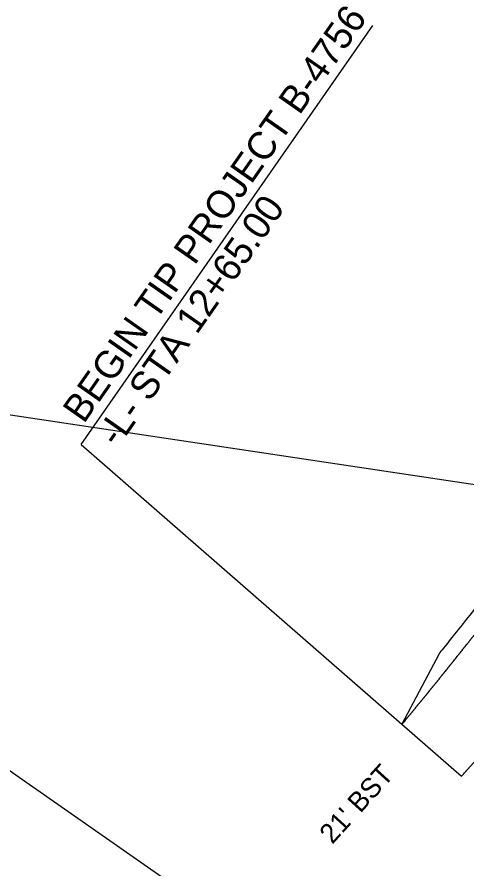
# Model space of a CAD drawing. Extents: x 1731327 to 1735374, y 884856 to 889832.
# Drawn here: x 1731918.7 to 1732032.5, y 885272.3 to 885487.7 of the extents above; entities that cross this region are included whole.
import ezdxf

# ---------------------------------------------------------------- set-up
doc = ezdxf.new("R2010")
doc.units = 0
for name, color, linetype in [('Exist Horizontal Baseline Alignment', 7, 'Continuous'), ('Exist Other Culture Area Outline', 7, 'Continuous'), ('Exist Other Culture Sign Text', 7, 'Continuous'), ('Exist Roads EOP', 7, 'Continuous'), ('Exist Structure Minor Pipes RCP 24 Inch', 7, 'Continuous'), ('Exist Structure Minor Pipes RCP 24 Inch Text', 7, 'Continuous')]:
    doc.layers.add(name, color=color, linetype=linetype)

msp = doc.modelspace()

# ---------------------------------------------------------------- linework, layer by layer
at = {"layer": 'Exist Other Culture Area Outline'}
for q in [(1732008.71, 885485.55), (1732016.04, 885308.91)]:
    msp.add_line((1731934.91, 885379.64), q, dxfattribs=at)
msp.add_lwpolyline([(1732238.91, 886072.74), (1731769.46, 885400.02), (1732118.14, 885156.7), (1732587.59, 885829.41)], close=True, dxfattribs=at)
at = {"layer": 'Exist Other Culture Sign Text'}
msp.add_lwpolyline([(1731775.28, 885408.36), (1732121.12, 885356.5), (1732232.4, 885320.42)], dxfattribs=at)
at = {"layer": 'Exist Structure Minor Pipes RCP 24 Inch'}
for p, q in [((1732025.45, 885326.74), (1732016.04, 885308.91)), ((1732016.04, 885308.91), (1732031.11, 885295.77))]:
    msp.add_line(p, q, dxfattribs=at)
for points, degree in [([(1732043.86, 885350.1), (1732038.81, 885343.58), (1732032.68, 885335.78), (1732026.49, 885328.04), (1732025.45, 885326.74)], 3), ([(1732036.84, 885334.63), (1732036.79, 885334.56), (1732036.73, 885334.49), (1732036.68, 885334.43), (1732036.54, 885334.25), (1732036.4, 885334.08), (1732036.27, 885333.9), (1732036.13, 885333.73), (1732035.99, 885333.55), (1732035.85, 885333.38), (1732035.71, 885333.2), (1732035.57, 885333.02), (1732035.43, 885332.85), (1732035.29, 885332.67), (1732035.15, 885332.5), (1732035.02, 885332.32), (1732034.88, 885332.15), (1732034.74, 885331.97), (1732034.6, 885331.8), (1732034.46, 885331.62), (1732034.32, 885331.45), (1732034.18, 885331.27), (1732034.04, 885331.09), (1732033.9, 885330.92), (1732033.76, 885330.74), (1732033.62, 885330.57), (1732033.48, 885330.39), (1732033.35, 885330.22), (1732033.21, 885330.04), (1732033.07, 885329.87), (1732032.93, 885329.69), (1732032.79, 885329.52), (1732032.65, 885329.34), (1732032.51, 885329.17), (1732032.37, 885328.99), (1732032.23, 885328.82), (1732032.09, 885328.64), (1732031.95, 885328.47), (1732031.81, 885328.29), (1732031.67, 885328.12), (1732031.53, 885327.94), (1732031.39, 885327.77), (1732031.25, 885327.59), (1732031.11, 885327.42), (1732030.97, 885327.24), (1732030.83, 885327.07), (1732030.69, 885326.89), (1732030.55, 885326.72), (1732030.41, 885326.54), (1732030.27, 885326.37), (1732030.13, 885326.19), (1732029.99, 885326.02), (1732029.85, 885325.84), (1732029.71, 885325.67), (1732029.57, 885325.49), (1732029.43, 885325.32), (1732029.29, 885325.14), (1732029.15, 885324.97), (1732029.01, 885324.79), (1732028.87, 885324.62), (1732028.73, 885324.45), (1732028.59, 885324.27), (1732028.45, 885324.1), (1732028.31, 885323.92), (1732028.17, 885323.75), (1732028.03, 885323.57), (1732027.89, 885323.4), (1732027.75, 885323.22), (1732027.61, 885323.05), (1732027.47, 885322.87), (1732027.33, 885322.7), (1732027.19, 885322.53), (1732027.05, 885322.35), (1732026.91, 885322.18), (1732026.77, 885322), (1732026.63, 885321.83), (1732026.6, 885321.78), (1732026.56, 885321.74), (1732026.53, 885321.7)], 3), ([(1732030.83, 885327.07), (1732030.97, 885327.24), (1732031.11, 885327.42), (1732031.25, 885327.59), (1732031.39, 885327.77), (1732031.53, 885327.94), (1732031.67, 885328.12), (1732031.81, 885328.29), (1732031.95, 885328.47), (1732032.09, 885328.64), (1732032.23, 885328.82), (1732032.37, 885328.99), (1732032.51, 885329.17)], 3), ([(1732032.51, 885329.17), (1732032.51, 885329.17), (1732032.51, 885329.17), (1732032.51, 885329.17), (1732032.51, 885329.17), (1732032.51, 885329.17), (1732032.51, 885329.17)], 3), ([(1732029.97, 885325.98), (1732029.98, 885325.99), (1732029.98, 885326.01), (1732029.99, 885326.02), (1732030.13, 885326.19), (1732030.27, 885326.37), (1732030.41, 885326.54), (1732030.55, 885326.72), (1732030.69, 885326.89), (1732030.83, 885327.07)], 3), ([(1732027.05, 885322.35), (1732027.19, 885322.53), (1732027.33, 885322.7), (1732027.47, 885322.87), (1732027.61, 885323.05), (1732027.75, 885323.22), (1732027.89, 885323.4), (1732028.03, 885323.57), (1732028.17, 885323.75), (1732028.31, 885323.92), (1732028.45, 885324.1), (1732028.59, 885324.27), (1732028.73, 885324.45), (1732028.87, 885324.62), (1732029.01, 885324.79), (1732029.15, 885324.97), (1732029.16, 885324.97), (1732029.16, 885324.97), (1732029.16, 885324.97)], 3), ([(1732029.16, 885324.97), (1732029.3, 885325.15), (1732029.44, 885325.32), (1732029.57, 885325.49), (1732029.71, 885325.66), (1732029.84, 885325.82), (1732029.97, 885325.98)], 3), ([(1732026.53, 885321.7), (1732026.56, 885321.74), (1732026.6, 885321.78), (1732026.63, 885321.83), (1732026.66, 885321.87), (1732026.7, 885321.91), (1732026.73, 885321.95)], 3), ([(1732026.73, 885321.95), (1732026.84, 885322.09), (1732026.94, 885322.22), (1732027.05, 885322.35), (1732027.05, 885322.35), (1732027.05, 885322.35), (1732027.05, 885322.35)], 3), ([(1732026.53, 885321.7), (1732026.42, 885321.57), (1732026.31, 885321.44), (1732026.21, 885321.31), (1732026.07, 885321.13), (1732025.93, 885320.96), (1732025.79, 885320.78), (1732025.65, 885320.61), (1732025.51, 885320.43), (1732025.37, 885320.26), (1732025.23, 885320.09), (1732025.08, 885319.91), (1732024.94, 885319.74), (1732024.8, 885319.57), (1732024.66, 885319.39), (1732024.52, 885319.22), (1732024.38, 885319.05), (1732024.24, 885318.87), (1732024.1, 885318.7), (1732023.96, 885318.53), (1732023.82, 885318.36), (1732023.68, 885318.18), (1732023.54, 885318.01), (1732023.4, 885317.84), (1732023.26, 885317.67), (1732023.12, 885317.49), (1732022.98, 885317.32), (1732022.84, 885317.15), (1732022.7, 885316.97), (1732022.56, 885316.8), (1732022.42, 885316.63), (1732022.28, 885316.46), (1732022.14, 885316.29), (1732022, 885316.11), (1732021.86, 885315.94), (1732021.72, 885315.77), (1732021.57, 885315.6), (1732021.43, 885315.42), (1732021.29, 885315.25), (1732021.15, 885315.08), (1732021.01, 885314.91), (1732020.87, 885314.74), (1732020.73, 885314.56), (1732020.59, 885314.39), (1732020.44, 885314.22), (1732020.3, 885314.05), (1732020.16, 885313.88), (1732020.02, 885313.71), (1732019.88, 885313.53), (1732019.74, 885313.36), (1732019.6, 885313.19), (1732019.45, 885313.02), (1732019.31, 885312.85), (1732019.17, 885312.68), (1732019.03, 885312.5), (1732018.89, 885312.33), (1732018.74, 885312.16), (1732018.6, 885311.99), (1732018.46, 885311.82), (1732018.32, 885311.65), (1732018.18, 885311.48), (1732018.03, 885311.3), (1732017.89, 885311.13), (1732017.75, 885310.96), (1732017.61, 885310.79), (1732017.47, 885310.62), (1732017.32, 885310.45), (1732017.18, 885310.28), (1732017.04, 885310.11), (1732016.9, 885309.94), (1732016.61, 885309.59), (1732016.32, 885309.25), (1732016.04, 885308.91)], 3), ([(1732024.52, 885319.22), (1732024.52, 885319.22), (1732024.52, 885319.22), (1732024.52, 885319.22), (1732024.66, 885319.39), (1732024.8, 885319.57), (1732024.94, 885319.74), (1732025.08, 885319.91), (1732025.23, 885320.09), (1732025.37, 885320.26), (1732025.51, 885320.43), (1732025.65, 885320.61), (1732025.79, 885320.78), (1732025.81, 885320.81), (1732025.84, 885320.84), (1732025.86, 885320.87)], 3), ([(1732025.86, 885320.87), (1732025.98, 885321.02), (1732026.09, 885321.16), (1732026.21, 885321.31), (1732026.31, 885321.44), (1732026.42, 885321.57), (1732026.53, 885321.7)], 3), ([(1732022.61, 885316.87), (1732022.69, 885316.96), (1732022.76, 885317.05), (1732022.84, 885317.15), (1732022.98, 885317.32), (1732023.12, 885317.49), (1732023.26, 885317.67), (1732023.4, 885317.84), (1732023.54, 885318.01), (1732023.68, 885318.18), (1732023.82, 885318.36), (1732023.96, 885318.53), (1732024.1, 885318.7), (1732024.24, 885318.87), (1732024.38, 885319.05), (1732024.52, 885319.22)], 3), ([(1732020.02, 885313.71), (1732020.11, 885313.82), (1732020.21, 885313.93), (1732020.3, 885314.05), (1732020.44, 885314.22), (1732020.59, 885314.39), (1732020.73, 885314.56), (1732020.87, 885314.74), (1732021.01, 885314.91), (1732021.15, 885315.08), (1732021.29, 885315.25), (1732021.43, 885315.42), (1732021.57, 885315.6), (1732021.72, 885315.77), (1732021.86, 885315.94), (1732022, 885316.11), (1732022.14, 885316.29), (1732022.28, 885316.46), (1732022.42, 885316.63), (1732022.48, 885316.71), (1732022.55, 885316.79), (1732022.61, 885316.87)], 3), ([(1732017.51, 885310.67), (1732017.59, 885310.77), (1732017.67, 885310.86), (1732017.75, 885310.96), (1732017.89, 885311.13), (1732018.03, 885311.3), (1732018.18, 885311.48), (1732018.32, 885311.65), (1732018.46, 885311.82), (1732018.6, 885311.99), (1732018.74, 885312.16), (1732018.89, 885312.33), (1732019.03, 885312.5), (1732019.17, 885312.68), (1732019.31, 885312.85), (1732019.45, 885313.02), (1732019.6, 885313.19), (1732019.74, 885313.36), (1732019.88, 885313.53), (1732019.93, 885313.59), (1732019.97, 885313.65), (1732020.02, 885313.71)], 3), ([(1732016.04, 885308.91), (1732016.32, 885309.25), (1732016.61, 885309.59), (1732016.9, 885309.94)], 2), ([(1732016.9, 885309.94), (1732017.03, 885310.1), (1732017.17, 885310.27), (1732017.31, 885310.43)], 2), ([(1732017.31, 885310.43), (1732017.31, 885310.44), (1732017.32, 885310.44), (1732017.32, 885310.45), (1732017.38, 885310.52), (1732017.44, 885310.6), (1732017.51, 885310.67)], 3), ([(1732017.31, 885310.43), (1732017.31, 885310.43), (1732017.31, 885310.43), (1732017.31, 885310.43)], 2), ([(1732031.11, 885295.77), (1732031.42, 885296.11), (1732031.73, 885296.44), (1732032.03, 885296.78), (1732032.19, 885296.95), (1732032.34, 885297.12), (1732032.49, 885297.29), (1732032.64, 885297.46), (1732032.8, 885297.63), (1732032.95, 885297.8), (1732033.1, 885297.97), (1732033.25, 885298.14), (1732033.41, 885298.31), (1732033.56, 885298.47), (1732033.71, 885298.64), (1732033.86, 885298.81), (1732034.02, 885298.98), (1732034.17, 885299.15), (1732034.32, 885299.32), (1732034.47, 885299.49), (1732034.63, 885299.66), (1732034.78, 885299.83), (1732034.93, 885300), (1732035.08, 885300.17), (1732035.23, 885300.34), (1732035.39, 885300.51), (1732035.54, 885300.68), (1732035.69, 885300.85), (1732035.84, 885301.02), (1732035.99, 885301.19), (1732036.14, 885301.36), (1732036.3, 885301.53), (1732036.45, 885301.7), (1732036.6, 885301.87), (1732036.75, 885302.04), (1732036.9, 885302.21), (1732037.05, 885302.38), (1732037.21, 885302.56), (1732037.36, 885302.73), (1732037.51, 885302.9), (1732037.66, 885303.07), (1732037.81, 885303.24), (1732037.96, 885303.41), (1732038.11, 885303.58), (1732038.26, 885303.75), (1732038.41, 885303.92), (1732038.57, 885304.09), (1732038.72, 885304.26), (1732038.87, 885304.43), (1732039.02, 885304.6), (1732039.17, 885304.78), (1732039.32, 885304.95), (1732039.47, 885305.12), (1732039.62, 885305.29), (1732039.77, 885305.46), (1732039.92, 885305.63), (1732040.07, 885305.8), (1732040.22, 885305.97), (1732040.37, 885306.15), (1732040.52, 885306.32), (1732040.68, 885306.49), (1732040.83, 885306.66), (1732040.97, 885306.83), (1732041.12, 885307), (1732041.27, 885307.17), (1732041.42, 885307.34), (1732041.57, 885307.51), (1732041.72, 885307.68), (1732041.87, 885307.85), (1732042.02, 885308.02), (1732042.11, 885308.12), (1732042.19, 885308.22), (1732042.28, 885308.32)], 3)]:
    msp.add_open_spline(points, degree=degree, dxfattribs=at)
at = {"layer": 'Exist Structure Minor Pipes RCP 24 Inch Text'}
msp.add_line((1732016.04, 885308.91), (1732031.11, 885295.77), dxfattribs=at)

# ---------------------------------------------------------------- texts
at = {"layer": 'Exist Horizontal Baseline Alignment'}
for s, p in [('BEGIN TIP PROJECT B-4756', (1731935.56, 885384.66)), ('-L- STA 12+65.00', (1731944.16, 885378.64))]:
    msp.add_text(s, height=7, rotation=55.0251, dxfattribs=at).set_placement(p)
at = {"layer": 'Exist Roads EOP'}
msp.add_text("21' BST", height=5, rotation=47.8342, dxfattribs=at).set_placement((1731998.43, 885278.41))

doc.saveas('drawing.dxf')
